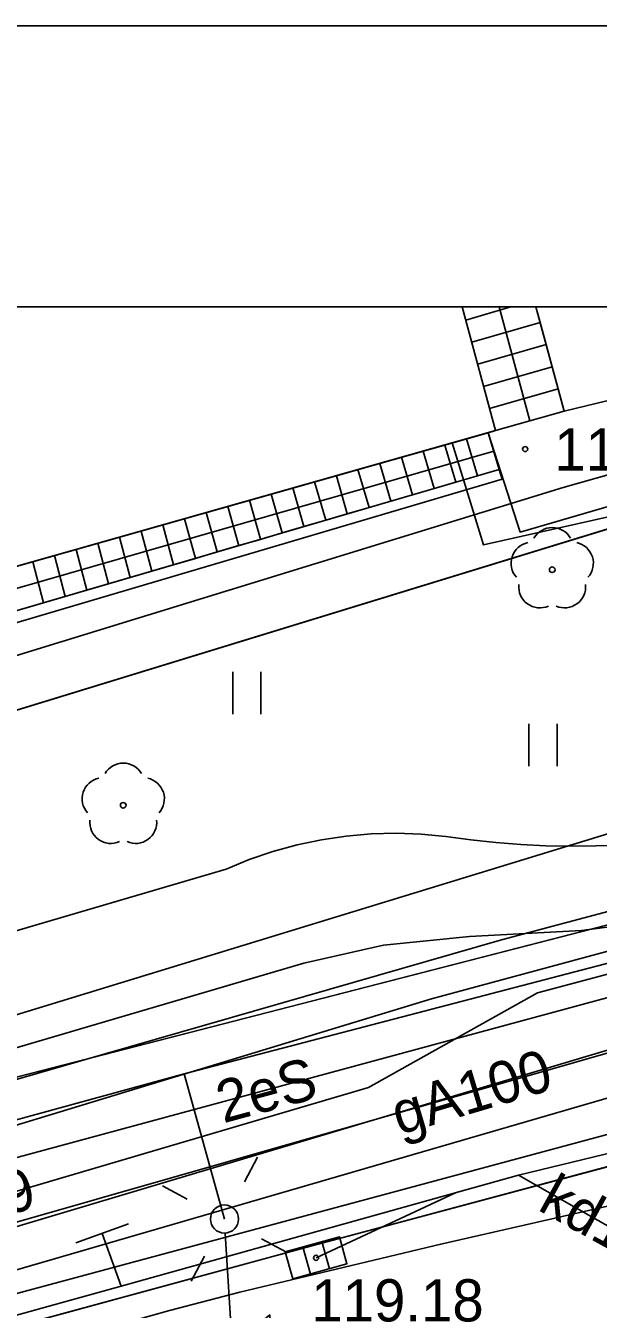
# Model space of a CAD drawing. Extents: x 6432121 to 6432331, y 5662538 to 5662686.
# Drawn here: x 6432193.67 to 6432203.86, y 5662663.23 to 5662686.05 of the extents above; entities that cross this region are included whole.
import ezdxf

# ---------------------------------------------------------------- set-up
doc = ezdxf.new("R2010")
doc.units = 0
for name, color, linetype in [('Warstwa 1', 7, 'Continuous'), ('Warstwa 10', 7, 'Continuous'), ('Warstwa 11', 7, 'Continuous'), ('Warstwa 12', 7, 'Continuous'), ('Warstwa 13', 7, 'Continuous'), ('Warstwa 14', 7, 'Continuous'), ('Warstwa 15', 7, 'Continuous'), ('Warstwa 19', 7, 'Continuous'), ('Warstwa 2', 7, 'Continuous'), ('Warstwa 36', 7, 'Continuous'), ('Warstwa 4', 7, 'Continuous'), ('Warstwa 40', 7, 'Continuous'), ('Warstwa 5', 7, 'Continuous'), ('Warstwa 6', 7, 'Continuous'), ('Warstwa 61', 7, 'Continuous'), ('Warstwa 63', 7, 'Continuous'), ('Warstwa 8', 7, 'Continuous'), ('Warstwa 9', 7, 'Continuous')]:
    doc.layers.add(name, color=color, linetype=linetype)

msp = doc.modelspace()

# ---------------------------------------------------------------- linework, layer by layer
at = {"layer": 'Warstwa 1'}
for p, q in [((6432136.78, 5662656.51), (6432207.04, 5662678.03)), ((6432136.78, 5662656.51), (6432207.04, 5662678.03)), ((6432183.398, 5662664.76), (6432232.544, 5662677.413)), ((6432183.398, 5662664.76), (6432232.544, 5662677.413))]:
    msp.add_line(p, q, dxfattribs=at)
msp.add_lwpolyline([(6432166.159, 5662681.053), (6432171.511, 5662675.224), (6432173.15, 5662676.497), (6432174.775, 5662674.789), (6432174.698, 5662674.488), (6432178.474, 5662673.461), (6432178.529, 5662673.7), (6432180.921, 5662674.296), (6432181.459, 5662673.034), (6432202.03, 5662678.854), (6432201.441, 5662681.053)], dxfattribs=at)
at = {"layer": 'Warstwa 10'}
for points in [[(6432178.835, 5662663.483), (6432179.667, 5662663.685), (6432183.376, 5662664.411), (6432187.121, 5662665.475), (6432194.656, 5662667.652), (6432202.136, 5662669.801), (6432216.655, 5662673.667), (6432220.668, 5662674.754), (6432223.415, 5662675.469), (6432239.794, 5662679.846), (6432240.486, 5662681.053)], [(6432125.976, 5662657.54), (6432137.66, 5662651.5), (6432142.32, 5662652.91), (6432165.05, 5662658.98), (6432185.52, 5662663.77), (6432211.24, 5662670.73), (6432230.88, 5662676.21), (6432235.66, 5662674.65)]]:
    msp.add_lwpolyline(points, dxfattribs=at)
at = {"layer": 'Warstwa 11'}
for centre in [(6432203.04, 5662676.382), (6432195.409, 5662672.194)]:
    msp.add_circle(centre, 0.05, dxfattribs=at)
for centre, start, end in [((6432203.04, 5662676.757), 30.1471, 149.8529), ((6432202.683, 5662676.498), 102.1471, 221.8529), ((6432203.397, 5662676.498), 318.1471, 77.8529), ((6432202.82, 5662676.079), 174.1471, 293.8529), ((6432203.26, 5662676.079), 246.1471, 5.8529), ((6432195.409, 5662672.569), 30.1471, 149.8529), ((6432195.052, 5662672.31), 102.1471, 221.8529), ((6432195.766, 5662672.31), 318.1471, 77.8529), ((6432195.189, 5662671.891), 174.1471, 293.8529), ((6432195.629, 5662671.891), 246.1471, 5.8529)]:
    msp.add_arc(centre, 0.375, start, end, dxfattribs=at)
at = {"layer": 'Warstwa 12'}
for points in [[(6432210.47, 5662681.053), (6432205.055, 5662673.029), (6432204.2, 5662671.738), (6432181.234, 5662664.72), (6432157.763, 5662657.531), (6432142.635, 5662652.934), (6432138.113, 5662652.263), (6432131.596, 5662652.74), (6432125.976, 5662654.881)], [(6432252.82, 5662681.053), (6432221.047, 5662671.933), (6432138.764, 5662648.032), (6432132.495, 5662646.498), (6432126.708, 5662647.568), (6432125.976, 5662647.734)], [(6432236.687, 5662681.053), (6432236.179, 5662680.268), (6432235.997, 5662679.964), (6432233.762, 5662674.712), (6432226.676, 5662672.867), (6432218.17, 5662670.615), (6432210.443, 5662668.5), (6432204.363, 5662665.144), (6432201.056, 5662664.395), (6432197.485, 5662663.542), (6432196.233, 5662663.213), (6432189.469, 5662661.315), (6432178.042, 5662658.146), (6432174.146, 5662657.07), (6432174.002, 5662656.976), (6432170.36, 5662653.903), (6432162.21, 5662651.482), (6432158.665, 5662650.451), (6432153.815, 5662649.037)], [(6432161.551, 5662681.053), (6432167.819, 5662674.322), (6432168.955, 5662673.173), (6432173.894, 5662667.86), (6432175.535, 5662666.115), (6432175.942, 5662663.535), (6432176.507, 5662663.465), (6432178.7, 5662662.668), (6432179.059, 5662662.663), (6432183.548, 5662663.582), (6432184.625, 5662663.866), (6432192.37, 5662666.167), (6432200.892, 5662668.754), (6432210.964, 5662671.473), (6432222.171, 5662674.51), (6432232.177, 5662677.188), (6432233.223, 5662677.473), (6432238.797, 5662677.192), (6432240.154, 5662672.977), (6432241.644, 5662668.194), (6432242.191, 5662665.717), (6432243.645, 5662658.765)], [(6432214.6, 5662681.053), (6432203.235, 5662677.843), (6432183.955, 5662671.923), (6432183.557, 5662671.545)], [(6432248.82, 5662629.93), (6432248.54, 5662629.72), (6432247.48, 5662630.2), (6432247.186, 5662630.33), (6432247.012, 5662630.407), (6432246.73, 5662630.84), (6432246.374, 5662630.582), (6432219.55, 5662620.66), (6432213.49, 5662610.33), (6432213.18, 5662609.798), (6432212.84, 5662609.97), (6432201.94, 5662619.39), (6432188.48, 5662659.63), (6432188.372, 5662660.264), (6432188.26, 5662660.96), (6432187.54, 5662663.58), (6432189.456, 5662664.144), (6432190.073, 5662664.038), (6432190.591, 5662664.478), (6432199.77, 5662667.18), (6432202.78, 5662668.86), (6432236.07, 5662677.73), (6432238.751, 5662681.053)], [(6432217.308, 5662675.659), (6432217.142, 5662676.313), (6432215.927, 5662680.339), (6432208.528, 5662678.44), (6432204.518, 5662677.431), (6432201.816, 5662676.824), (6432201.263, 5662678.637)], [(6432126.82, 5662648.145), (6432127.178, 5662648.008), (6432131.097, 5662647.505), (6432133.122, 5662647.201), (6432135.028, 5662647.845), (6432148.121, 5662651.554), (6432159.913, 5662655.046), (6432176.332, 5662659.768), (6432190.085, 5662663.807), (6432202.171, 5662667.26), (6432216.316, 5662671.31), (6432225.518, 5662674.016), (6432231.508, 5662675.69), (6432243.068, 5662679.006)], [(6432129.02, 5662644.49), (6432128.8, 5662645.29), (6432133.76, 5662648.23), (6432151.52, 5662653.14), (6432168.26, 5662658.24), (6432174.11, 5662659.65), (6432182.72, 5662662.19), (6432184.64, 5662664.15), (6432186.13, 5662664.58), (6432196.49, 5662667.42), (6432210.64, 5662671.11), (6432218.98, 5662673.5), (6432219.48, 5662674.07), (6432230.96, 5662676.8), (6432232.45, 5662677.97)], [(6432125.976, 5662645.74), (6432131.623, 5662647.083), (6432138.492, 5662648.808), (6432146.028, 5662650.541), (6432153.864, 5662652.39), (6432160.763, 5662654.062), (6432162.516, 5662654.48), (6432167.591, 5662655.857), (6432175.21, 5662658.015), (6432175.71, 5662658.12), (6432181.929, 5662659.868), (6432191.24, 5662662.505), (6432195.372, 5662663.644), (6432202.44, 5662665.619), (6432204.153, 5662666.037), (6432209.479, 5662667.515)], [(6432197.21, 5662664.84), (6432196.49, 5662667.42)], [(6432202.44, 5662665.619), (6432205.619, 5662663.813)], [(6432198.84, 5662664.15), (6432201.321, 5662665.306)]]:
    msp.add_lwpolyline(points, dxfattribs=at)
at = {"layer": 'Warstwa 13'}
msp.add_circle((6432202.559, 5662678.526), 0.045, dxfattribs=at)
at = {"layer": 'Warstwa 14'}
msp.add_circle((6432198.84, 5662664.15), 0.045, dxfattribs=at)
at = {"layer": 'Warstwa 19'}
for p, q in [((6432194.564, 5662664.416), (6432195.505, 5662664.754)), ((6432195.372, 5662663.644), (6432195.034, 5662664.585))]:
    msp.add_line(p, q, dxfattribs=at)
at = {"layer": 'Warstwa 2'}
for points in [[(6432201.9, 5662678.817), (6432202.47, 5662677.05), (6432207.96, 5662678.65)], [(6432204.57, 5662666.49), (6432179.48, 5662659.74), (6432149.1, 5662650.42)]]:
    msp.add_lwpolyline(points, dxfattribs=at)
msp.add_circle((6432197.21, 5662664.84), 0.25, dxfattribs=at)
at = {"layer": 'Warstwa 36'}
for p, q in [((6432201.503, 5662680.821), (6432202.302, 5662681.053)), ((6432201.609, 5662680.428), (6432202.825, 5662680.779)), ((6432201.714, 5662680.035), (6432202.933, 5662680.385)), ((6432201.819, 5662679.641), (6432203.04, 5662679.991)), ((6432201.925, 5662679.247), (6432203.147, 5662679.596)), ((6432201.514, 5662678.707), (6432201.712, 5662678.05)), ((6432200.357, 5662678.38), (6432200.554, 5662677.712)), ((6432200.742, 5662678.49), (6432200.939, 5662677.824)), ((6432201.128, 5662678.598), (6432201.326, 5662677.938)), ((6432199.585, 5662678.162), (6432199.781, 5662677.486)), ((6432199.971, 5662678.271), (6432200.168, 5662677.599)), ((6432198.814, 5662677.944), (6432199.01, 5662677.261)), ((6432199.2, 5662678.052), (6432199.395, 5662677.373)), ((6432198.043, 5662677.725), (6432198.237, 5662677.035)), ((6432198.428, 5662677.835), (6432198.623, 5662677.148)), ((6432197.271, 5662677.507), (6432197.465, 5662676.809)), ((6432197.657, 5662677.616), (6432197.85, 5662676.923)), ((6432196.5, 5662677.289), (6432196.692, 5662676.584)), ((6432196.886, 5662677.398), (6432197.079, 5662676.697)), ((6432195.729, 5662677.07), (6432195.92, 5662676.358)), ((6432196.114, 5662677.18), (6432196.306, 5662676.471)), ((6432194.957, 5662676.853), (6432195.148, 5662676.133)), ((6432195.343, 5662676.962), (6432195.534, 5662676.246)), ((6432194.186, 5662676.634), (6432194.376, 5662675.907)), ((6432194.572, 5662676.744), (6432194.761, 5662676.02)), ((6432193.8, 5662676.525), (6432193.99, 5662675.795))]:
    msp.add_line(p, q, dxfattribs=at)
msp.add_lwpolyline([(6432201.441, 5662681.053), (6432202.03, 5662678.854), (6432203.254, 5662679.202), (6432202.751, 5662681.053)], dxfattribs=at)
msp.add_lwpolyline([(6432181.459, 5662673.034), (6432201.9, 5662678.817), (6432202.099, 5662678.163), (6432181.633, 5662672.186)], close=True, dxfattribs=at)
at = {"layer": 'Warstwa 4'}
for p, q in [((6432198.604, 5662664.344), (6432198.739, 5662663.862)), ((6432198.941, 5662664.438), (6432199.076, 5662663.956))]:
    msp.add_line(p, q, dxfattribs=at)
for points in [[(6432201.441, 5662681.053), (6432202.03, 5662678.854), (6432181.459, 5662673.034), (6432180.921, 5662674.296), (6432178.529, 5662673.7), (6432178.474, 5662673.461), (6432174.698, 5662674.488), (6432174.775, 5662674.789), (6432173.15, 5662676.497), (6432177.276, 5662681.053)], [(6432197.564, 5662665.501), (6432197.8, 5662665.942)], [(6432196.549, 5662665.194), (6432196.108, 5662665.43)], [(6432197.871, 5662664.486), (6432198.312, 5662664.25)], [(6432196.856, 5662664.179), (6432196.62, 5662663.738)]]:
    msp.add_lwpolyline(points, dxfattribs=at)
msp.add_lwpolyline([(6432198.291, 5662664.256), (6432199.254, 5662664.526), (6432199.389, 5662664.044), (6432198.426, 5662663.774)], close=True, dxfattribs=at)
msp.add_circle((6432197.21, 5662664.84), 0.25, dxfattribs=at)
at = {"layer": 'Warstwa 40'}
msp.add_lwpolyline([(6432197.225, 5662664.59), (6432197.347, 5662662.594), (6432198.015, 5662663.136), (6432198.137, 5662661.14)], dxfattribs=at)
msp.add_circle((6432197.21, 5662664.84), 0.25, dxfattribs=at)
at = {"layer": 'Warstwa 5'}
for p, q in [((6432203.254, 5662679.202), (6432207.083, 5662680.119)), ((6432202.03, 5662678.854), (6432203.254, 5662679.202)), ((6432201.9, 5662678.817), (6432202.03, 5662678.854)), ((6432201.9, 5662678.817), (6432202.099, 5662678.163)), ((6432202.099, 5662678.163), (6432202.15, 5662677.993)), ((6432181.767, 5662671.976), (6432202.15, 5662677.993)), ((6432197.359, 5662673.814), (6432197.359, 5662674.564)), ((6432197.859, 5662673.814), (6432197.859, 5662674.564)), ((6432202.626, 5662672.89), (6432202.626, 5662673.64)), ((6432203.126, 5662672.89), (6432203.126, 5662673.64)), ((6432198.501, 5662671.49), (6432198.936, 5662671.582)), ((6432198.936, 5662671.582), (6432199.376, 5662671.647)), ((6432199.376, 5662671.647), (6432199.819, 5662671.686)), ((6432199.819, 5662671.686), (6432200.263, 5662671.697)), ((6432200.263, 5662671.697), (6432200.707, 5662671.682)), ((6432200.707, 5662671.682), (6432201.15, 5662671.64)), ((6432201.15, 5662671.64), (6432201.592, 5662671.58)), ((6432201.592, 5662671.58), (6432202.035, 5662671.532)), ((6432202.035, 5662671.532), (6432202.479, 5662671.498)), ((6432197.651, 5662671.229), (6432198.072, 5662671.372)), ((6432198.072, 5662671.372), (6432198.501, 5662671.49)), ((6432202.479, 5662671.498), (6432202.925, 5662671.476)), ((6432202.925, 5662671.476), (6432203.37, 5662671.467)), ((6432203.37, 5662671.467), (6432203.816, 5662671.471)), ((6432203.816, 5662671.471), (6432204.261, 5662671.488)), ((6432197.24, 5662671.06), (6432197.651, 5662671.229)), ((6432183.048, 5662666.886), (6432197.24, 5662671.06)), ((6432127.12, 5662644.89), (6432204.32, 5662667.93)), ((6432198.79, 5662664.37), (6432204.85, 5662665.99)), ((6432185.89, 5662660.86), (6432198.79, 5662664.37))]:
    msp.add_line(p, q, dxfattribs=at)
at = {"layer": 'Warstwa 6'}
for points in [[(6432139.86, 5662681.053), (6432132.84, 5662660.45), (6432136.78, 5662656.51), (6432207.04, 5662678.03), (6432217.416, 5662681.053)], [(6432217.416, 5662681.053), (6432207.04, 5662678.03), (6432136.78, 5662656.51), (6432134.43, 5662655.74), (6432136.954, 5662653.004), (6432164.325, 5662660.371), (6432183.398, 5662664.76), (6432232.544, 5662677.413), (6432235.366, 5662681.053)], [(6432164.06, 5662654.4), (6432171.72, 5662656.75), (6432178.39, 5662658.77), (6432185.89, 5662660.86), (6432198.79, 5662664.37), (6432204.85, 5662665.99), (6432210.65, 5662667.56), (6432213.18, 5662668.19), (6432238.51, 5662675.09), (6432238.854, 5662675.652), (6432239.185, 5662676.222), (6432239.503, 5662676.799), (6432239.808, 5662677.384), (6432240.099, 5662677.975), (6432240.377, 5662678.572), (6432240.642, 5662679.176), (6432240.893, 5662679.785), (6432241.13, 5662680.4), (6432241.403, 5662681.053)]]:
    msp.add_lwpolyline(points, dxfattribs=at)
msp.add_lwpolyline([(6432234.842, 5662644.244), (6432245.39, 5662639.916), (6432244.087, 5662648.722), (6432241.262, 5662679.658), (6432232.544, 5662677.413), (6432183.398, 5662664.76), (6432164.325, 5662660.371), (6432136.954, 5662653.004), (6432141.907, 5662600.47), (6432147.05, 5662605.45), (6432164.332, 5662622.19), (6432166.394, 5662623.975)], close=True, dxfattribs=at)
at = {"layer": 'Warstwa 61'}
for points in [[(6432202.642, 5662679.028), (6432202.096, 5662681.053)], [(6432202, 5662678.49), (6432181.546, 5662672.61)]]:
    msp.add_lwpolyline(points, dxfattribs=at)
at = {"layer": 'Warstwa 63'}
for points in [[(6432120.976, 5662686.053), (6432330.976, 5662686.053), (6432330.976, 5662537.553), (6432120.976, 5662537.553)], [(6432125.976, 5662556.053), (6432325.976, 5662556.053), (6432325.976, 5662681.053), (6432125.976, 5662681.053)]]:
    msp.add_lwpolyline(points, close=True, dxfattribs=at)
at = {"layer": 'Warstwa 8'}
for p, q in [((6432198.79, 5662664.37), (6432204.85, 5662665.99)), ((6432185.89, 5662660.86), (6432198.79, 5662664.37))]:
    msp.add_line(p, q, dxfattribs=at)
at = {"layer": 'Warstwa 9'}
for p, q in [((6432202.751, 5662681.053), (6432202.825, 5662680.779)), ((6432202.825, 5662680.779), (6432202.932, 5662680.385)), ((6432202.932, 5662680.385), (6432203.04, 5662679.991)), ((6432203.04, 5662679.991), (6432203.147, 5662679.596)), ((6432203.254, 5662679.202), (6432207.083, 5662680.119)), ((6432203.147, 5662679.596), (6432203.254, 5662679.202)), ((6432201.712, 5662678.05), (6432202.099, 5662678.163)), ((6432202.099, 5662678.163), (6432202.15, 5662677.993)), ((6432181.767, 5662671.976), (6432202.15, 5662677.993)), ((6432200.939, 5662677.824), (6432201.326, 5662677.937)), ((6432201.326, 5662677.937), (6432201.712, 5662678.05)), ((6432200.168, 5662677.599), (6432200.554, 5662677.712)), ((6432200.554, 5662677.712), (6432200.939, 5662677.824)), ((6432199.395, 5662677.373), (6432199.781, 5662677.486)), ((6432199.781, 5662677.486), (6432200.168, 5662677.599)), ((6432198.623, 5662677.148), (6432199.01, 5662677.261)), ((6432199.01, 5662677.261), (6432199.395, 5662677.373)), ((6432197.85, 5662676.922), (6432198.237, 5662677.035)), ((6432198.237, 5662677.035), (6432198.623, 5662677.148)), ((6432197.079, 5662676.697), (6432197.465, 5662676.81)), ((6432197.465, 5662676.81), (6432197.85, 5662676.922)), ((6432196.306, 5662676.471), (6432196.692, 5662676.584)), ((6432196.692, 5662676.584), (6432197.079, 5662676.697)), ((6432195.534, 5662676.246), (6432195.92, 5662676.358)), ((6432195.92, 5662676.358), (6432196.306, 5662676.471)), ((6432194.761, 5662676.02), (6432195.148, 5662676.133)), ((6432195.148, 5662676.133), (6432195.534, 5662676.246)), ((6432193.99, 5662675.795), (6432194.376, 5662675.907)), ((6432194.376, 5662675.907), (6432194.761, 5662676.02)), ((6432193.603, 5662675.682), (6432193.99, 5662675.795)), ((6432198.501, 5662671.49), (6432198.936, 5662671.582)), ((6432198.936, 5662671.582), (6432199.376, 5662671.647)), ((6432199.376, 5662671.647), (6432199.819, 5662671.686)), ((6432199.819, 5662671.686), (6432200.263, 5662671.697)), ((6432200.263, 5662671.697), (6432200.707, 5662671.682)), ((6432200.707, 5662671.682), (6432201.15, 5662671.64)), ((6432201.15, 5662671.64), (6432201.592, 5662671.58)), ((6432201.592, 5662671.58), (6432202.035, 5662671.532)), ((6432202.035, 5662671.532), (6432202.479, 5662671.498)), ((6432197.651, 5662671.229), (6432198.072, 5662671.372)), ((6432198.072, 5662671.372), (6432198.501, 5662671.49)), ((6432202.479, 5662671.498), (6432202.925, 5662671.476)), ((6432202.925, 5662671.476), (6432203.37, 5662671.467)), ((6432203.37, 5662671.467), (6432203.816, 5662671.471)), ((6432203.816, 5662671.471), (6432204.261, 5662671.488)), ((6432197.24, 5662671.06), (6432197.651, 5662671.229)), ((6432183.048, 5662666.886), (6432197.24, 5662671.06)), ((6432203.56, 5662669.97), (6432205.3, 5662670.19)), ((6432203.56, 5662669.97), (6432205.3, 5662670.19)), ((6432201.57, 5662669.86), (6432203.56, 5662669.97)), ((6432201.57, 5662669.86), (6432203.56, 5662669.97)), ((6432198.62, 5662669.39), (6432200.04, 5662669.71)), ((6432198.62, 5662669.39), (6432200.04, 5662669.71)), ((6432200.04, 5662669.71), (6432201.57, 5662669.86)), ((6432200.04, 5662669.71), (6432201.57, 5662669.86)), ((6432176.23, 5662662.8), (6432198.62, 5662669.39)), ((6432176.23, 5662662.8), (6432198.62, 5662669.39)), ((6432127.12, 5662644.89), (6432204.32, 5662667.93))]:
    msp.add_line(p, q, dxfattribs=at)

# ---------------------------------------------------------------- texts
at = {"layer": 'Warstwa 11'}
msp.add_text('2eS', height=0.75, rotation=15.1433, dxfattribs=at).set_placement((6432197.188, 5662666.539))
at = {"layer": 'Warstwa 13'}
msp.add_text('119.4', height=0.75, dxfattribs=at).set_placement((6432203.076, 5662678.144))
for s, rotation, p in [('gA100', 16.6444, (6432200.318, 5662666.327)), ('kd150', 331.1009, (6432202.759, 5662665.012))]:
    msp.add_text(s, height=0.75, rotation=rotation, dxfattribs=at).set_placement(p)
at = {"layer": 'Warstwa 14'}
msp.add_text('118.29', height=0.75, rotation=16.4038, dxfattribs=at).set_placement((6432190.961, 5662664.196))
at = {"layer": 'Warstwa 15'}
msp.add_text('119.18', height=0.75, dxfattribs=at).set_placement((6432198.754, 5662663.019))

doc.saveas('drawing.dxf')
